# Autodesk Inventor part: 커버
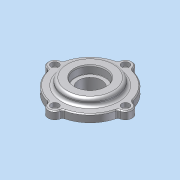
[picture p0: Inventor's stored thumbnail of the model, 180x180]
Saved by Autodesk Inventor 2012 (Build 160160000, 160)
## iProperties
Company: 한국ATC센터
Created: 2015-03
Part Number: 커버
Document SubType Name: Modeling
Designer: KYOUNG IL JANG
Density: 1 g/cm^3
Material: 기본값
Author: KYOUNG IL JANG
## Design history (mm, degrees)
sketch "스케치1"
  geometry: C1 r 1.621 at (0, 6.75) reference; C2 r 1.621 at (-37, -30.25) reference; C3 r 1.621 at (0, -67.25) reference; C4 r 1.621 at (37, -30.25) reference; C5 r 10 at (0, -30.25) reference; C6 r 12 at (0, -30.25); C7 r 24.5 at (0, -30.25) reference; A1 r 3 centre (-38.77, -20.408) between (-38.239, -23.361) and (-35.862, -21.146) reference; A2 r 7 centre (-37, -30.25) between (-38.239, -23.361) and (-38.239, -37.139) reference; A3 r 3 centre (-38.77, -40.092) between (-35.862, -39.354) and (-38.239, -37.139) reference; A4 r 37 centre (0, -30.25) between (-35.862, -39.354) and (-9.104, -66.113) reference; A5 r 3 centre (-9.842, -69.02) between (-6.889, -68.489) and (-9.104, -66.113) reference; A6 r 7 centre (0, -67.25) between (-6.889, -68.489) and (6.889, -68.489) reference; A7 r 3 centre (9.842, -69.02) between (9.104, -66.112) and (6.889, -68.489) reference; A8 r 37 centre (0, -30.25) between (9.104, -66.112) and (35.863, -39.354) reference; A9 r 3 centre (38.77, -40.092) between (38.239, -37.139) and (35.863, -39.354) reference; A10 r 7 centre (37, -30.25) between (38.239, -37.139) and (38.239, -23.361) reference; A11 r 3 centre (38.77, -20.408) between (35.863, -21.146) and (38.239, -23.361) reference; A12 r 37 centre (0, -30.25) between (35.863, -21.146) and (9.104, 5.612) reference; A13 r 3 centre (9.842, 8.52) between (6.889, 7.989) and (9.104, 5.612) reference; A14 r 7 centre (0, 6.75) between (6.889, 7.989) and (-6.889, 7.989) reference; A15 r 3 centre (-9.842, 8.52) between (-9.104, 5.612) and (-6.889, 7.989) reference; A16 r 37 centre (0, -30.25) between (-9.104, 5.612) and (-35.862, -21.146) reference; 1 further point
  constraints: 1 centre point, 1 coincident
  dimensions: "d2" = 2 radial gap between concentric circles of C6 C5
extrude "돌출1" new body sketch "스케치1" distance "d0" = 8; taper "d1" = 0 deg
sketch "스케치2"
  geometry: C1 r 23.5 at (0, -30.25) reference; C2 r 12 at (0, -30.25) reference; 1 further point
extrude "돌출2" join sketch "스케치2" distance "d4" = 5; taper "d5" = 0 deg
sketch "스케치3"
  geometry: C1 r 23.5 at (0, 0) reference; C2 r 20.5 at (0, 0); 1 further point
  constraints: 1 centre point
  dimensions: "d6" = 3 radial gap between concentric circles of C2 C1
node "작업 평면1"
extrude "돌출3" join sketch "스케치3" stored distance "d7" = 5; taper "d8" = 0 deg
fillet "모깎기1" dims "d9" = 3
sketch "스케치4"
  geometry: C1 r 12 at (0, -30.25) reference; C2 r 27 at (0, -30.25); 1 further point
  constraints: 1 centre point
  dimensions: "d10" = 15 radial gap between concentric circles of C1 C2
extrude "돌출4" join sketch "스케치4" distance "d11" = 7; taper "d12" = 0 deg
fillet "모깎기2" dims "d13" = 3
chamfer "모따기1" distance "d14" = 1; stored, may be unused: second distance "d15" = 2, angle "d16" = 45 deg
node "작업점1"
  node "작업축1"
chamfer "모따기2" distance "d24" = 1; stored, may be unused: second distance "d25" = 2, angle "d26" = 45 deg
hole "구멍6" diameter "d43" = 4.5; stored, may be unused: countersink angle "d47" = 90 deg, drill point angle "d49" = 118 deg; dims "d41" = 10, "d42" = 10, "d44" = 6, "d45" = 8, "d46" = 4.4, "d48" = 8
sketch "스케치8"
  geometry: C1 r 12 at (0, 0) reference; C2 r 16 at (0, 0); 1 further point
  constraints: 1 centre point, 1 coincident
  dimensions: "d53" = 32 diameter of C2
extrude "돌출5" cut sketch "스케치8" distance "d54" = 8.3; taper "d55" = 0 deg
fillet "모깎기3" dims "d56" = 0.3
chamfer "모따기3" distance "d57" = 1.2; stored, may be unused: second distance "d58" = 2, angle "d59" = 30 deg
node "솔리드1"
pattern_circular "원형 패턴1" dims angle "d51" = 360 deg
node "참조1"
node "참조2"
